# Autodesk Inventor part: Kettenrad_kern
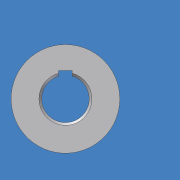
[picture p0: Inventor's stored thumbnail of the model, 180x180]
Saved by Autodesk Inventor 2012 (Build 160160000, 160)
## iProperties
Company: CAD-Verlag
Part Number: Kettenrad_kern
Document SubType Name: Modeling
Created: 2004-09
Material: Standard
Designer: Greiling
Manufacturer: Standard
Standards Organization: Custom
Density: 1 g/cm^3
Control State: 0
Master: False
Checked Out: False
Shininess: 64.0
Length Units: 11269
Angle Units: 11279
Time Units: 11290
Mass Units: 11283
Length Display Precision: 3
Angle Display Precision: 2
Compacted: True
Density: 0.0
Volumn: 0.0
Area: 0.0
PropertySet Name: Model Information
Author: Jürgen Kronas
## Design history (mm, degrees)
sketch "Skizze1"
  geometry: L1 (0, 52)-(0, -4) reference; L2 (-43.2, 0)-(57.6, 0) reference; L3 (-43.2, 0)-(57.6, 0) reference; L4 (0, -4)-(0, 52) reference; L5 (-36, 19.5)-(-36, 40); L6 (-36, 40)-(36, 40); L7 (36, 40)-(36, 19.5); L8 (-36, 0)-(36, 0); L9 (-34, 17.5)-(34, 17.5); L10 (-34, 17.5)-(-36, 19.5); L11 (34, 17.5)-(36, 19.5); 5 further points
  constraints: 14 end point, 12 point on line, 2 parallel, 2 perpendicular, 1 collinear, 1 other
  dimensions: "d0" = 72 distance of L5.end L6.end; "d1" = 80 diameter of L6 L8; "d2" = 35 diameter of L9 L2; "d3" = 2 distance of L9.start point (-36, 17.5); "d4" = 2 distance of L5.start point (-36, 17.5) (= d3); "d5" = 2 distance of L9.end point (36, 17.5) (= d3); "d6" = 2 distance of L7.end point (36, 17.5) (= d5)
revolve "Drehung1" sketch "Skizze1" stored, may be unused: angle "d7" = 90 deg
sketch "Skizze2"
  geometry: L1 (-5, 16.771)-(-5, 20.8); L2 (-5, 20.8)-(5, 20.8); L3 (5, 20.8)-(5, 16.771); L4 (0, 64)-(0, -48) reference; L5 (-48, 0)-(64, 0) reference; L6 (0, -48)-(0, 64) reference; L7 (-48, 0)-(64, 0) reference; A1 r 17.5 centre (0, 0) between (-5, 16.771) and (5, 16.771) reference
  constraints: 6 end point, 2 point on circle, 1 parallel, 1 perpendicular, 1 vertical, 1 other
  dimensions: "d9" = 20.8 distance from line of A1.centre L2; "d10" = 10 distance of L1.end L2.end
extrude "Extrusion1" cut sketch "Skizze2" stored distance "d11" = 10; taper "d12" = 0 deg
node "Volumenkörper1"
node "Volumenkörpern"
node "Oberflächenkörpern"
